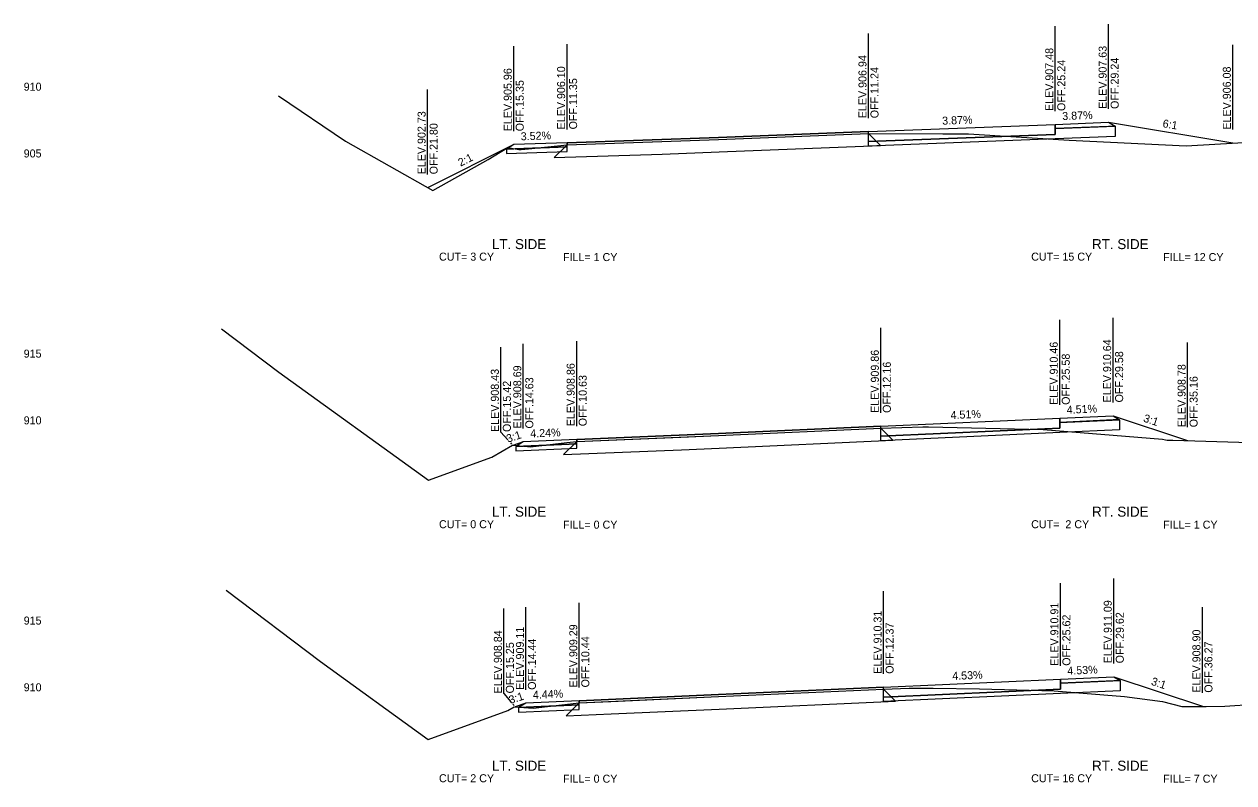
# Model space of a CAD drawing. Extents: x -4 to 359, y 0 to 1436.
# Drawn here: x -3.9 to 86.8, y 173.1 to 230 of the extents above; entities that cross this region are included whole.
import ezdxf

# ---------------------------------------------------------------- set-up
doc = ezdxf.new("R2010")
doc.units = 0
for name, color, linetype in [('XS-Existing subsurface-pavement', 7, 'Continuous'), ('XS-Existing surface-ground', 7, 'Continuous'), ('XS-Proposed Finish Grade', 7, 'Continuous'), ('XS-Proposed subsurface-aggregate layer 1', 7, 'Continuous'), ('XS-Proposed surface-ground', 7, 'Continuous'), ('XS-Proposed surface-pavement', 7, 'Continuous'), ('XS-Proposed surface-shoulder', 7, 'Continuous'), ('XS-Text-ditch slope', 7, 'Continuous'), ('XS-Text-earthwork labels', 7, 'Continuous'), ('XS-Text-elevation', 7, 'Continuous'), ('XS-Text-pavement elevation', 7, 'Continuous'), ('XS-Text-pavement slope', 7, 'Continuous'), ('XS-Text-profile report', 7, 'Continuous'), ('XS-Text-shoulder elevation', 7, 'Continuous'), ('XS-Text-shoulder slope', 7, 'Continuous'), ('XS-Text-tie elevation', 7, 'Continuous'), ('XS-Text-tie offset', 7, 'Continuous')]:
    doc.layers.add(name, color=color, linetype=linetype)

msp = doc.modelspace()

# ---------------------------------------------------------------- linework, layer by layer
at = {"layer": 'XS-Existing subsurface-pavement'}
for p, q in [((59.37, 221.785), (60.273, 220.882)), ((36.78, 220.95), (35.81, 219.98)), ((43.911, 220.249), (48.166, 220.414)), ((48.166, 220.414), (60.273, 220.882)), ((35.81, 219.98), (43.906, 220.249)), ((60.294, 199.707), (61.192, 198.809)), ((37.498, 198.708), (36.519, 197.729)), ((48.172, 198.223), (61.192, 198.809)), ((36.519, 197.729), (45.347, 198.096)), ((45.35, 198.096), (48.172, 198.223)), ((60.501, 180.162), (61.399, 179.264)), ((37.695, 179.138), (36.715, 178.159)), ((40.095, 178.3), (48.172, 178.665)), ((48.172, 178.665), (61.399, 179.264)), ((36.715, 178.159), (40.092, 178.3))]:
    msp.add_line(p, q, dxfattribs=at)
at = {"layer": 'XS-Existing surface-ground'}
for p, q in [((15.151, 224.6), (20.18, 221.205)), ((83.188, 220.869), (109.093, 222.41)), ((43.875, 221.186), (48.13, 221.35)), ((48.13, 221.35), (59.37, 221.785)), ((59.37, 221.785), (64.937, 221.764)), ((64.937, 221.764), (66.865, 221.771)), ((66.865, 221.771), (74.423, 221.289)), ((74.423, 221.289), (83.188, 220.869)), ((20.18, 221.205), (26.712, 217.509)), ((30.875, 219.841), (32.343, 220.73)), ((32.343, 220.73), (33.161, 220.591)), ((33.161, 220.591), (33.346, 220.585)), ((33.346, 220.585), (33.878, 220.635)), ((33.878, 220.635), (36.78, 220.95)), ((36.78, 220.95), (43.875, 221.186)), ((26.712, 217.509), (30.875, 219.841)), ((10.884, 207.158), (15.179, 203.906)), ((15.179, 203.906), (26.391, 195.803)), ((48.13, 199.16), (60.294, 199.707)), ((60.294, 199.707), (63.452, 199.809)), ((63.452, 199.809), (63.871, 199.808)), ((63.871, 199.808), (72.454, 199.605)), ((72.454, 199.605), (81.399, 198.874)), ((34.026, 198.302), (36.761, 198.627)), ((36.761, 198.627), (37.498, 198.708)), ((37.498, 198.708), (45.308, 199.033)), ((45.308, 199.033), (48.13, 199.16)), ((81.399, 198.874), (81.639, 198.841)), ((81.639, 198.841), (81.762, 198.811)), ((81.762, 198.811), (81.862, 198.809)), ((81.862, 198.809), (82.17, 198.812)), ((82.17, 198.812), (91.223, 198.533)), ((31.131, 197.531), (32.682, 198.425)), ((32.682, 198.425), (33.816, 198.337)), ((33.816, 198.337), (34.026, 198.302)), ((26.391, 195.803), (31.131, 197.531)), ((11.217, 187.566), (18.286, 182.216)), ((18.286, 182.216), (26.357, 176.385)), ((40.053, 179.237), (48.13, 179.602)), ((48.13, 179.602), (60.501, 180.162)), ((60.501, 180.162), (62.42, 180.226)), ((62.42, 180.226), (64.214, 180.239)), ((64.214, 180.239), (67.681, 180.172)), ((67.681, 180.172), (73.293, 180.041)), ((73.293, 180.041), (78.551, 179.613)), ((78.551, 179.613), (81.399, 179.23)), ((32.338, 178.567), (32.815, 178.842)), ((32.815, 178.842), (34.226, 178.727)), ((34.226, 178.727), (37.472, 179.113)), ((37.472, 179.113), (37.695, 179.138)), ((37.695, 179.138), (40.053, 179.237)), ((81.399, 179.23), (82.864, 178.864)), ((82.864, 178.864), (83.273, 178.859)), ((83.273, 178.859), (84.675, 178.868)), ((84.675, 178.868), (86.072, 178.889)), ((86.072, 178.889), (88.361, 179.034)), ((26.357, 176.385), (32.338, 178.567))]:
    msp.add_line(p, q, dxfattribs=at)
at = {"layer": 'XS-Proposed Finish Grade'}
for points in [[(59.37, 221.931), (73.37, 222.473)], [(73.37, 222.473), (77.37, 222.628)], [(36.78, 221.096), (48.13, 221.495), (59.37, 221.931)], [(36.78, 221.096), (32.78, 220.955)], [(60.294, 199.853), (73.706, 200.457)], [(73.706, 200.457), (77.706, 200.637)], [(37.498, 198.854), (48.13, 199.305), (60.294, 199.853)], [(37.498, 198.854), (33.498, 198.684)], [(60.501, 180.307), (73.753, 180.908)], [(73.753, 180.908), (77.753, 181.089)], [(37.695, 179.284), (48.125, 179.747), (60.501, 180.307)], [(37.695, 179.284), (33.695, 179.106)]]:
    msp.add_lwpolyline(points, dxfattribs=at)
at = {"layer": 'XS-Proposed subsurface-aggregate layer 1'}
for points in [[(73.37, 222.161), (77.86, 222.335)], [(73.37, 221.723), (73.37, 222.161)], [(77.86, 222.335), (77.86, 221.564)], [(59.37, 221.181), (73.37, 221.723)], [(77.86, 221.564), (73.37, 221.39), (59.37, 220.847)], [(36.78, 220.783), (32.227, 220.623)], [(32.227, 220.623), (32.227, 220.29)], [(32.227, 220.29), (36.78, 220.45)], [(36.78, 220.45), (36.78, 220.783)], [(59.37, 220.847), (59.37, 221.181)], [(60.294, 199.103), (73.706, 199.707)], [(78.19, 199.576), (73.706, 199.374), (60.294, 198.77)], [(73.706, 200.145), (78.19, 200.347)], [(73.706, 199.707), (73.706, 200.145)], [(78.19, 200.347), (78.19, 199.576)], [(60.294, 198.77), (60.294, 199.103)], [(37.498, 198.541), (32.937, 198.348)], [(32.937, 198.348), (32.937, 198.015)], [(32.937, 198.015), (37.498, 198.208)], [(37.498, 198.208), (37.498, 198.541)], [(73.753, 180.595), (78.237, 180.798)], [(73.753, 180.158), (73.753, 180.595)], [(78.237, 180.798), (78.237, 180.027)], [(60.501, 179.557), (73.753, 180.158)], [(78.237, 180.027), (73.753, 179.824), (60.501, 179.224)], [(60.501, 179.224), (60.501, 179.557)], [(37.695, 178.971), (33.132, 178.769)], [(33.132, 178.769), (33.132, 178.436)], [(33.132, 178.436), (37.695, 178.638)], [(37.695, 178.638), (37.695, 178.971)]]:
    msp.add_lwpolyline(points, dxfattribs=at)
at = {"layer": 'XS-Proposed surface-ground'}
for points in [[(77.37, 222.628), (86.678, 221.077)], [(32.78, 220.955), (26.326, 217.728)], [(77.706, 200.637), (83.287, 198.777)], [(33.498, 198.684), (32.707, 198.423)], [(77.753, 181.089), (84.473, 178.867)], [(33.695, 179.106), (32.88, 178.837)]]:
    msp.add_lwpolyline(points, dxfattribs=at)
at = {"layer": 'XS-Proposed surface-pavement'}
for points in [[(59.37, 221.931), (73.37, 222.473)], [(73.37, 222.473), (73.37, 221.723)], [(59.37, 221.931), (48.13, 221.495), (36.78, 221.096)], [(36.78, 220.95), (48.13, 221.349), (59.37, 221.785)], [(59.37, 221.181), (59.37, 221.931)], [(59.37, 221.785), (59.37, 221.931)], [(73.37, 221.723), (59.37, 221.181)], [(36.78, 221.096), (36.78, 220.95)], [(60.294, 199.853), (73.706, 200.457)], [(73.706, 200.457), (73.706, 199.707)], [(60.294, 199.853), (48.13, 199.305), (37.498, 198.854)], [(37.498, 198.708), (48.13, 199.159), (60.294, 199.707)], [(60.294, 199.103), (60.294, 199.853)], [(60.294, 199.707), (60.294, 199.853)], [(73.706, 199.707), (60.294, 199.103)], [(37.498, 198.854), (37.498, 198.708)], [(60.501, 180.307), (73.753, 180.908)], [(73.753, 180.908), (73.753, 180.158)], [(60.501, 180.307), (48.125, 179.747), (37.695, 179.284)], [(37.695, 179.138), (48.125, 179.601), (60.501, 180.162)], [(60.501, 179.557), (60.501, 180.307)], [(60.501, 180.162), (60.501, 180.307)], [(73.753, 180.158), (60.501, 179.557)], [(37.695, 179.284), (37.695, 179.138)]]:
    msp.add_lwpolyline(points, dxfattribs=at)
at = {"layer": 'XS-Proposed surface-shoulder'}
for points in [[(73.37, 222.473), (77.37, 222.628), (77.86, 222.335)], [(73.37, 222.161), (73.37, 222.473)], [(77.86, 222.335), (77.37, 222.316), (73.37, 222.161)], [(36.78, 221.096), (32.78, 220.955), (32.227, 220.623)], [(32.227, 220.623), (32.78, 220.643), (36.78, 220.783)], [(36.78, 220.783), (36.78, 221.096)], [(73.706, 200.457), (77.706, 200.637), (78.19, 200.347)], [(73.706, 200.145), (73.706, 200.457)], [(78.19, 200.347), (77.706, 200.325), (73.706, 200.145)], [(37.498, 198.854), (33.498, 198.684), (32.937, 198.348)], [(37.498, 198.541), (37.498, 198.854)], [(32.937, 198.348), (33.498, 198.372), (37.498, 198.541)], [(73.753, 180.908), (77.753, 181.089), (78.237, 180.798)], [(73.753, 180.595), (73.753, 180.908)], [(78.237, 180.798), (77.753, 180.776), (73.753, 180.595)], [(37.695, 179.284), (33.695, 179.106), (33.132, 178.769)], [(33.132, 178.769), (33.695, 178.794), (37.695, 178.971)], [(37.695, 178.971), (37.695, 179.284)]]:
    msp.add_lwpolyline(points, dxfattribs=at)
at = {"layer": 'XS-Text-tie offset'}
for p, q in [((73.37, 223.473), (73.37, 229.823)), ((77.37, 223.628), (77.37, 229.978)), ((36.78, 222.096), (36.78, 228.494)), ((59.37, 222.931), (59.37, 229.281)), ((32.78, 221.955), (32.78, 228.333)), ((86.678, 222.077), (86.678, 228.427)), ((26.326, 218.728), (26.326, 225.078)), ((73.706, 201.457), (73.706, 207.835)), ((77.706, 201.637), (77.706, 207.987)), ((60.294, 200.853), (60.294, 207.231)), ((33.498, 199.684), (33.498, 206.034)), ((37.498, 199.854), (37.498, 206.232)), ((83.287, 199.777), (83.287, 206.127)), ((31.815, 199.423), (31.815, 205.773)), ((31.815, 199.423), (32.346, 198.828)), ((32.55, 198.6), (32.62, 198.521)), ((73.753, 181.908), (73.753, 188.108)), ((77.753, 182.089), (77.753, 188.439)), ((60.501, 181.307), (60.501, 187.508)), ((32.042, 179.837), (32.042, 186.187)), ((33.695, 180.106), (33.695, 186.306)), ((37.695, 180.284), (37.695, 186.634)), ((84.399, 179.891), (84.399, 186.289)), ((32.042, 179.837), (32.568, 179.21)), ((32.71, 179.04), (32.803, 178.929))]:
    msp.add_line(p, q, dxfattribs=at)

# ---------------------------------------------------------------- texts
at = {"layer": 'XS-Text-ditch slope'}
for s, rotation, p in [('6:1', 350.53766, (81.383, 222.263)), ('2:1', 26.56505, (28.793, 219.297)), ('3:1', 341.56507, (79.927, 200.213)), ('3:1', 18.26289, (32.344, 198.619)), ('3:1', 341.70379, (80.506, 180.495)), ('3:1', 18.26285, (32.528, 179.037))]:
    msp.add_text(s, height=0.6, rotation=rotation, dxfattribs=at).set_placement(p)
at = {"layer": 'XS-Text-earthwork labels'}
for s, height, p in [('LT. SIDE', 0.75, (31.148, 213.127)), ('RT. SIDE', 0.75, (76.127, 213.127)), (' CUT= 3 CY           ', 0.6, (26.96, 212.262)), ('FILL= 1 CY           ', 0.6, (36.472, 212.23)), (' CUT= 15 CY           ', 0.6, (71.341, 212.262)), ('FILL= 12 CY           ', 0.6, (81.452, 212.23)), ('LT. SIDE', 0.75, (31.148, 193.078)), ('RT. SIDE', 0.75, (76.127, 193.078)), (' CUT= 0 CY           ', 0.6, (26.96, 192.213)), ('FILL= 0 CY           ', 0.6, (36.472, 192.181)), (' CUT=  2 CY           ', 0.6, (71.341, 192.213)), ('FILL= 1 CY           ', 0.6, (81.452, 192.181)), ('LT. SIDE', 0.75, (31.148, 174.045)), ('RT. SIDE', 0.75, (76.127, 174.045)), (' CUT= 2 CY           ', 0.6, (26.96, 173.18)), ('FILL= 0 CY           ', 0.6, (36.472, 173.148)), (' CUT= 16 CY           ', 0.6, (71.341, 173.18)), ('FILL= 7 CY           ', 0.6, (81.452, 173.148))]:
    msp.add_text(s, height=height, dxfattribs=at).set_placement(p)
at = {"layer": 'XS-Text-elevation'}
for s, p in [('           910           ', (-6.4, 224.995)), ('           905           ', (-6.4, 219.995)), ('           915           ', (-6.4, 204.995)), ('           910           ', (-6.4, 199.995)), ('           915           ', (-6.4, 184.995)), ('           910           ', (-6.4, 179.995))]:
    msp.add_text(s, height=0.6, dxfattribs=at).set_placement(p)
at = {"layer": 'XS-Text-pavement elevation'}
for s, p in [('ELEV.906.94', (59.22, 222.931)), ('ELEV.907.48', (73.22, 223.473)), ('ELEV.906.10', (36.63, 222.096)), ('OFF.11.24', (60.12, 222.931)), ('OFF.25.24', (74.12, 223.473)), ('ELEV.905.96', (32.63, 221.955)), ('OFF.15.35', (33.53, 221.955)), ('OFF.11.35', (37.53, 222.096)), ('ELEV.910.46', (73.556, 201.457)), ('ELEV.909.86', (60.144, 200.853)), ('OFF.25.58', (74.456, 201.457)), ('ELEV.908.69', (33.348, 199.684)), ('ELEV.908.86', (37.348, 199.854)), ('OFF.12.16', (61.044, 200.853)), ('OFF.14.63', (34.248, 199.684)), ('OFF.10.63', (38.248, 199.854)), ('ELEV.910.31', (60.351, 181.307)), ('ELEV.910.91', (73.603, 181.908)), ('ELEV.909.29', (37.545, 180.284)), ('OFF.12.37', (61.251, 181.307)), ('OFF.25.62', (74.503, 181.908)), ('ELEV.909.11', (33.545, 180.106)), ('OFF.10.44', (38.445, 180.284)), ('OFF.14.44', (34.445, 180.106))]:
    msp.add_text(s, height=0.6, rotation=90, dxfattribs=at).set_placement(p)
at = {"layer": 'XS-Text-pavement slope'}
for s, rotation, p in [('3.87%', 2.21896, (64.903, 222.445)), ('4.51%', 2.57996, (65.532, 200.389)), ('4.53%', 2.59351, (65.659, 180.841))]:
    msp.add_text(s, height=0.6, rotation=rotation, dxfattribs=at).set_placement(p)
at = {"layer": 'XS-Text-profile report'}
for s, p in [('Shldr_Surf_Asph_B111', (73.354, 222.16)), ('Pvmt_Surf_Conc_T1_R', (73.355, 222.472)), ('Shldr_Surf_Asph_T11', (77.355, 222.627)), ('Shldr_Surf_Asph_B11', (77.355, 222.315)), ('Shldr_Surf_Asph_B21', (77.844, 222.334)), ('Pvmt_Surf_Asph_T1', (48.116, 221.494)), ('Pvmt_Surf_Asph_T', (48.117, 221.348)), ('Pvmt_Surf_Asph_T1_R', (59.354, 221.93)), ('Pvmt_Surf_Asph_T_R', (59.355, 221.784)), ('Pvmt_Surf_Conc_B1_R', (73.355, 221.722)), ('Agg_Layer_1_B11', (73.358, 221.389)), ('Agg_Layer_1_B12', (77.848, 221.563)), ('Rt_Agg_Layer_1_B13', (82.63, 221.748)), ('Shldr_Surf_Asph_B2', (32.212, 220.622)), ('Shldr_Surf_Asph_T1', (32.766, 220.954)), ('Shldr_Surf_Asph_B1', (32.766, 220.642)), ('Pvmt_Surf_Asph_T2_L', (36.765, 221.095)), ('Shldr_Surf_Asph_B12', (36.765, 220.782)), ('Pvmt_Surf_Asph_T_L', (36.765, 220.949)), ('Agg_Layer_1_B', (36.77, 220.449)), ('Pvmt_Surf_Conc_B_R', (59.355, 221.18)), ('Agg_Layer_1_B2', (59.358, 220.846)), ('Fill_Slope_2_B1', (86.666, 221.076)), ('Agg_Layer_1_B1', (32.216, 220.289)), ('Fill_Slope_2_B', (26.314, 217.727)), ('Fill_Slope_2_B', (26.314, 217.727)), ('Pvmt_Surf_Conc_T1_R', (73.69, 200.456)), ('Shldr_Surf_Asph_T11', (77.691, 200.637)), ('Pvmt_Surf_Asph_T1_R', (60.278, 199.852)), ('Pvmt_Surf_Asph_T_R', (60.279, 199.706)), ('Shldr_Surf_Asph_B111', (73.69, 200.144)), ('Pvmt_Surf_Conc_B1_R', (73.69, 199.706)), ('Shldr_Surf_Asph_B11', (77.691, 200.324)), ('Shldr_Surf_Asph_B21', (78.175, 200.346)), ('Agg_Layer_1_B12', (78.178, 199.575)), ('Rt_Agg_Layer_1_B13', (80.554, 199.682)), ('Shldr_Surf_Asph_T1', (33.483, 198.683)), ('Pvmt_Surf_Asph_T2_L', (37.482, 198.853)), ('Pvmt_Surf_Asph_T_L', (37.483, 198.707)), ('Pvmt_Surf_Asph_T1', (48.116, 199.304)), ('Pvmt_Surf_Asph_T', (48.117, 199.158)), ('Pvmt_Surf_Conc_B_R', (60.279, 199.102)), ('Agg_Layer_1_B2', (60.282, 198.769)), ('Agg_Layer_1_B11', (73.694, 199.373)), ('Fill_Slope_2_B1', (83.275, 198.776)), ('Fill_Slope_2_B', (32.696, 198.423)), ('Shldr_Surf_Asph_B2', (32.923, 198.347)), ('Agg_Layer_1_B1', (32.926, 198.014)), ('Shldr_Surf_Asph_B1', (33.483, 198.371)), ('Shldr_Surf_Asph_B12', (37.482, 198.541)), ('Agg_Layer_1_B', (37.487, 198.207)), ('Shldr_Surf_Asph_B111', (73.737, 180.594)), ('Pvmt_Surf_Conc_T1_R', (73.738, 180.907)), ('Shldr_Surf_Asph_T11', (77.738, 181.088)), ('Shldr_Surf_Asph_B11', (77.738, 180.775)), ('Shldr_Surf_Asph_B21', (78.222, 180.797)), ('Pvmt_Surf_Asph_T1', (48.112, 179.746)), ('Pvmt_Surf_Asph_T', (48.112, 179.6)), ('Pvmt_Surf_Asph_T1_R', (60.486, 180.307)), ('Pvmt_Surf_Asph_T_R', (60.487, 180.161)), ('Pvmt_Surf_Conc_B_R', (60.487, 179.557)), ('Pvmt_Surf_Conc_B1_R', (73.738, 180.157)), ('Agg_Layer_1_B11', (73.741, 179.824)), ('Agg_Layer_1_B12', (78.225, 180.027)), ('Rt_Agg_Layer_1_B13', (80.619, 180.135)), ('Fill_Slope_2_B', (32.868, 178.837)), ('Shldr_Surf_Asph_B2', (33.118, 178.768)), ('Shldr_Surf_Asph_T1', (33.68, 179.105)), ('Shldr_Surf_Asph_B1', (33.68, 178.793)), ('Pvmt_Surf_Asph_T2_L', (37.679, 179.283)), ('Shldr_Surf_Asph_B12', (37.679, 178.971)), ('Pvmt_Surf_Asph_T_L', (37.68, 179.137)), ('Agg_Layer_1_B', (37.684, 178.637)), ('Agg_Layer_1_B2', (60.49, 179.223)), ('Fill_Slope_2_B1', (84.461, 178.866)), ('Agg_Layer_1_B1', (33.121, 178.435))]:
    msp.add_text(s, height=0.00167, dxfattribs=at).set_placement(p)
at = {"layer": 'XS-Text-shoulder elevation'}
for s, p in [('ELEV.907.63', (77.22, 223.628)), ('OFF.29.24', (78.12, 223.628)), ('ELEV.910.64', (77.556, 201.637)), ('OFF.29.58', (78.456, 201.637)), ('ELEV.911.09', (77.603, 182.089)), ('OFF.29.62', (78.503, 182.089))]:
    msp.add_text(s, height=0.6, rotation=90, dxfattribs=at).set_placement(p)
at = {"layer": 'XS-Text-shoulder slope'}
for s, rotation, p in [('3.87%', 2.21896, (73.904, 222.794)), ('3.52%', 2.01463, (33.314, 221.274)), ('4.51%', 2.57996, (74.238, 200.782)), ('4.24%', 2.42835, (34.03, 199.007)), ('4.53%', 2.59351, (74.285, 181.232)), ('4.44%', 2.54174, (34.226, 179.43))]:
    msp.add_text(s, height=0.6, rotation=rotation, dxfattribs=at).set_placement(p)
at = {"layer": 'XS-Text-tie elevation'}
for s, p in [('ELEV.906.08', (86.528, 222.077)), ('ELEV.902.73', (26.176, 218.728)), ('OFF.21.80', (27.076, 218.728)), ('ELEV.908.43', (31.665, 199.423)), ('ELEV.908.78', (83.137, 199.777)), ('OFF.15.42', (32.565, 199.423)), ('OFF.35.16', (84.037, 199.777)), ('ELEV.908.84', (31.892, 179.837)), ('ELEV.908.90', (84.249, 179.891)), ('OFF.15.25', (32.792, 179.837)), ('OFF.36.27', (85.149, 179.891))]:
    msp.add_text(s, height=0.6, rotation=90, dxfattribs=at).set_placement(p)

doc.saveas('drawing.dxf')
